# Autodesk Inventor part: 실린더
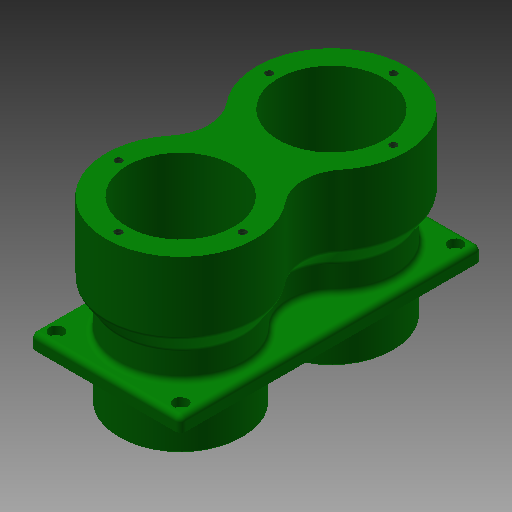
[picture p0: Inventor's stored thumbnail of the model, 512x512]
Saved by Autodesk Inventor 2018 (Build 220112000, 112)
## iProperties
Created: 2016-11
Part Number: 실린더
Material: 알루미늄 6061
Document SubType Name: Modeling
Designer: mduedu
Density: 2.71 g/cm^3
Mass: 1199.26 g
Surface Area: 1038.68 cm^2
Volume: 442.531 cm^3
Appearance: 진녹색
Author: mduedu
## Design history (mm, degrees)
sketch "스케치1"
  geometry: L1 (0, 0)-(0, 101); L2 (30, 0)-(30, 101); L3 (30, 101)-(42, 101); L4 (42, 101)-(42, 61); L5 (42, 61)-(35, 51); L6 (35, 51)-(35, 0); L7 (35, 0)-(30, 0)
  constraints: 14 end point, 4 parallel, 2 horizontal alignment, 1 perpendicular, 1 vertical
  dimensions: "d0" = 101 distance of L1.start L1.end; "d1" = 60 diameter of L2.end L1; "d2" = 84 diameter of L3.end L1; "d3" = 70 diameter of L6.end L1; "d4" = 40 distance of L3.end L4.end; "d5" = 50 vertical distance of L5.end L3.end
revolve "회전1" stored, may be unused: angle "d6" = 90 deg
node "작업 평면1"
sketch "스케치2"
  geometry: L1 (-42.5, -42.5)-(42.5, -42.5); L2 (42.5, -42.5)-(42.5, 42.5); L3 (42.5, 42.5)-(-42.5, 42.5); L4 (-42.5, 42.5)-(-42.5, -42.5); L5 (-42.5, -42.5)-(42.5, 42.5); L6 (42.5, -42.5)-(-42.5, 42.5); C1 r 35 at (0, 0) reference; C2 r 35 at (0, 0); 1 further point
  constraints: 12 end point, 2 midpoint, 2 parallel, 2 perpendicular, 1 centre point, 1 coincident, 1 concentric, 1 horizontal
  dimensions: "d8" = 85 distance of L2.end L3.end
extrude "돌출1" join sketch "스케치2" distance "d10" = 8; taper "d11" = 0 deg
chamfer "모따기1" distance "d14" = 1; stored, may be unused: second distance "d15" = 2, angle "d16" = 45 deg
chamfer "모따기2" distance "d17" = 5; stored, may be unused: second distance "d18" = 2, angle "d19" = 15 deg
sketch "스케치3"
  geometry: L1 (-35, -35)-(35, -35); L2 (35, -35)-(35, 35); L3 (35, 35)-(-35, 35); L4 (-35, 35)-(-35, -35); L5 (-35, -35)-(35, 35); L6 (35, -35)-(-35, 35); 3 further points
  constraints: 12 end point, 2 coincident, 2 midpoint, 2 parallel, 1 horizontal, 1 perpendicular
  dimensions: "d20" = 70 distance of L3.end L2.end; "d21" = 70 distance of L2.end L1.end
sketch "스케치4"
  geometry: 2 further points
  constraints: 2 other
hole "구멍1" sketch "스케치4" at (-35, 35), (35, 35) diameter "d22" = 4.5; stored, may be unused: countersink angle "d26" = 90 deg, drill point angle "d28" = 0 deg; dims "d23" = 6, "d24" = 8, "d25" = 4.6, "d27" = 8
sketch "스케치5"
  geometry: 3 further points
  constraints: 3 other
hole "구멍2" sketch "스케치5" at (35, 0), (-35, 0), (0, 35) diameter "d29" = 4.134; stored, may be unused: countersink angle "d33" = 90 deg, drill point angle "d35" = 120 deg; dims "d30" = 7.5, "d31" = 4, "d32" = 2, "d34" = 10
fillet "모깎기3" dims "d36" = 3
fillet "모깎기4" dims "d37" = 3
sketch "스케치6"
  geometry: L1 (0, 0)-(0, -85); A1 r 42 centre (0, 0) between (32.469, -26.642) and (-32.469, -26.642) reference; A2 r 42 centre (0, -85) between (32.469, -58.358) and (-32.469, -58.358) reference; A3 r 25 centre (51.795, -42.5) between (32.469, -58.358) and (32.469, -26.642); A4 r 25 centre (-51.795, -42.5) between (-32.469, -26.642) and (-32.469, -58.358); A5 r 25 centre (51.795, -42.5) between (32.469, -26.642) and (32.469, -58.358); A6 r 25 centre (-51.795, -42.5) between (-32.469, -58.358) and (-32.469, -26.642); A7 r 42 centre (0, 0) between (-32.469, -26.642) and (32.469, -26.642); A8 r 42 centre (0, -85) between (32.469, -58.358) and (-32.469, -58.358); A9 r 42 centre (0, 0) between (32.469, -26.642) and (-32.469, -26.642); A10 r 42 centre (0, -85) between (-32.469, -58.358) and (32.469, -58.358); 1 further point
  constraints: 20 point on circle, 8 centre point, 2 coincident, 2 end point, 2 tangent, 1 symmetric about line, 1 vertical, 1 other
  dimensions: "d38" = 50 diameter of A3
node "작업 평면2"
sketch "스케치7"
  geometry: A1 r 25 centre (9.795, -42.5) between (-9.531, -26.642) and (-9.531, -58.358) reference; A2 r 42 centre (-42, 0) between (-74.469, -26.642) and (-9.531, -26.642) reference; A3 r 42 centre (-42, -85) between (-9.531, -58.358) and (-74.469, -58.358) reference; A4 r 25 centre (-93.795, -42.5) between (-74.469, -58.358) and (-74.469, -26.642) reference; 1 further point
node "작업 평면3"
sketch "스케치8"
  geometry: L1 (-35, 0)-(-35, -85); A1 r 35 centre (-35, 0) between (-10.294, -24.792) and (-59.706, -24.792) reference; A2 r 35 centre (-35, -85) between (-10.294, -60.208) and (-59.706, -60.208) reference; A3 r 25 centre (7.353, -42.5) between (-10.294, -60.208) and (-10.294, -24.792); A4 r 25 centre (-77.353, -42.5) between (-59.706, -24.792) and (-59.706, -60.208); A5 r 25 centre (7.353, -42.5) between (-10.294, -24.792) and (-10.294, -60.208); A6 r 25 centre (-77.353, -42.5) between (-59.706, -60.208) and (-59.706, -24.792); A7 r 35 centre (-35, 0) between (-59.706, -24.792) and (-10.294, -24.792); A8 r 35 centre (-35, -85) between (-10.294, -60.208) and (-59.706, -60.208); 1 further point
  constraints: 16 point on circle, 6 centre point, 2 coincident, 2 end point, 2 tangent, 1 symmetric about line, 1 vertical, 1 other
  dimensions: "d40" = 50 diameter of A3
sketch "스케치9"
  geometry: A1 r 25 centre (42.353, -42.5) between (24.706, -24.792) and (24.706, -60.208) reference; A2 r 35 centre (0, 0) between (-24.706, -24.792) and (24.706, -24.792) reference; A3 r 35 centre (0, -85) between (24.706, -60.208) and (-24.706, -60.208) reference; A4 r 25 centre (-42.353, -42.5) between (-24.706, -60.208) and (-24.706, -24.792) reference; 1 further point
feature "로프트1" sketch "스케치8", "스케치9" dims "d42" = 0, "d43" = 90 deg, "d44" = 0, "d45" = 90 deg
feature "로프트2" dims "d46" = 0, "d47" = 90 deg, "d48" = 0, "d49" = 90 deg
  node "모서리1"
feature "로프트3" dims "d50" = 0, "d51" = 90 deg, "d52" = 0, "d53" = 90 deg
  node "모서리2"
fillet "모깎기5" dims "d54" = 3
node "솔리드1"
mirror "대칭1"
other parameters: "d7" = -27
